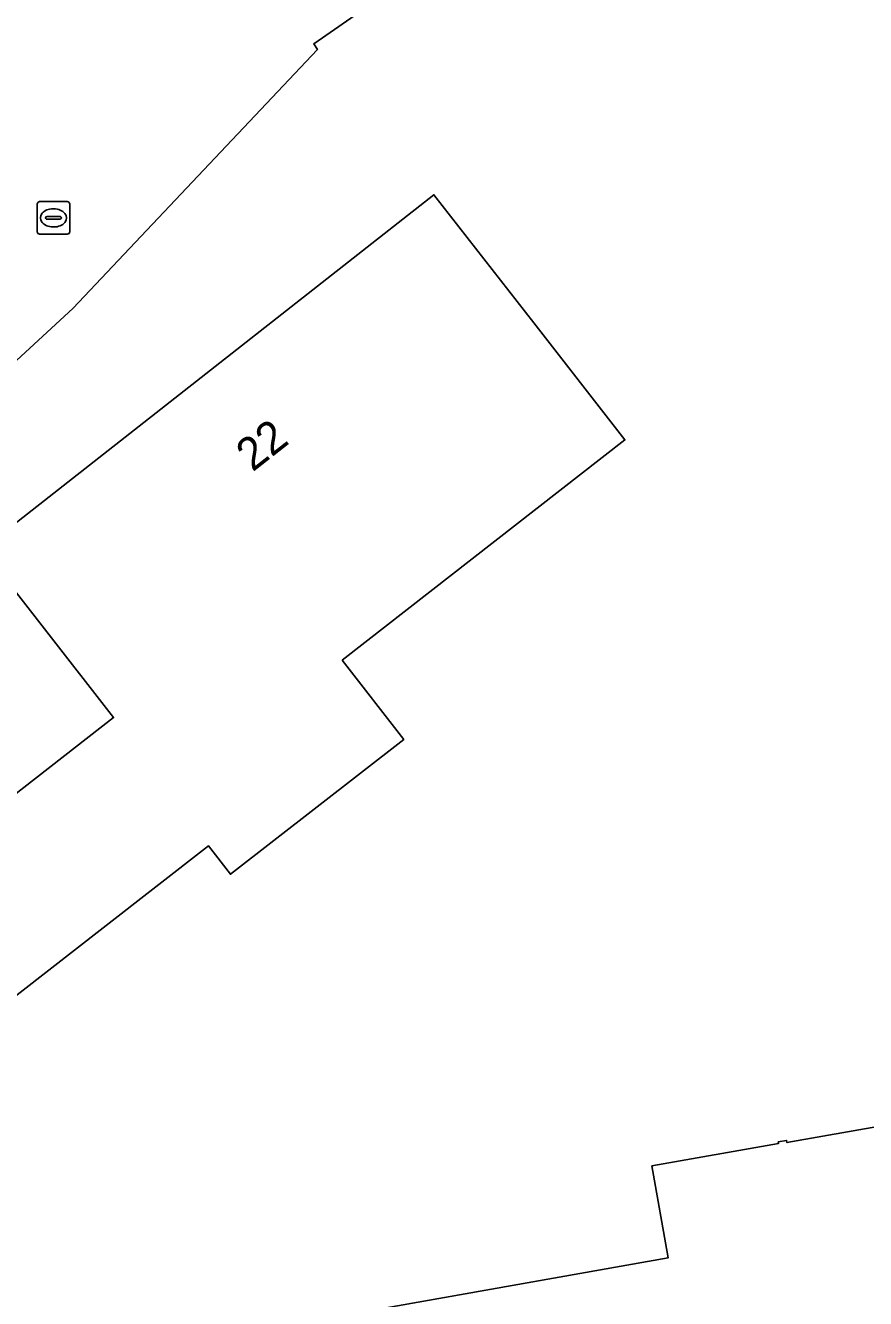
# Model space of a CAD drawing. Extents: x 162879 to 165540, y 384011 to 385181.
# Drawn here: x 164259.38 to 164285.23, y 384298.69 to 384337.86 of the extents above; entities that cross this region are included whole.
import ezdxf

# ---------------------------------------------------------------- set-up
doc = ezdxf.new("R2010")
doc.units = 0
for name, color, linetype in [('IMGEO_Brandkraan', 7, 'Continuous'), ('IMGEO_Erf', 7, 'Continuous'), ('IMGEO_Pand', 7, 'Continuous'), ('IMGEO_Pand_nummerreeks', 7, 'Continuous'), ('IMGEO_Voetpad_open', 7, 'Continuous')]:
    doc.layers.add(name, color=color, linetype=linetype)

msp = doc.modelspace()

# ---------------------------------------------------------------- linework, layer by layer
at = {"layer": 'IMGEO_Brandkraan'}
for p, q in [((164259.745, 384331.517), (164259.745, 384332.369)), ((164259.82, 384332.443), (164260.672, 384332.443)), ((164260.746, 384332.369), (164260.746, 384331.517)), ((164260.047, 384331.986), (164260.445, 384331.986)), ((164260.233, 384332.223), (164260.258, 384332.223)), ((164260.004, 384331.937), (164260.004, 384331.949)), ((164260.442, 384331.9), (164260.044, 384331.9)), ((164260.256, 384331.663), (164260.231, 384331.663)), ((164260.488, 384331.949), (164260.488, 384331.937)), ((164260.672, 384331.443), (164259.82, 384331.443))]:
    msp.add_line(p, q, dxfattribs=at)
for points in [[(164259.745, 384331.517), (164259.745, 384332.369)], [(164259.82, 384332.443), (164260.672, 384332.443)], [(164260.746, 384332.369), (164260.746, 384331.517)], [(164260.672, 384331.443), (164259.82, 384331.443)]]:
    msp.add_lwpolyline(points, dxfattribs=at)
for centre, radius, start, end in [((164259.822, 384332.367), 0.0765, 91.552, 178.448), ((164259.822, 384332.367), 0.0765, 91.552, 178.448), ((164260.67, 384332.367), 0.0765, 1.552, 88.448), ((164260.67, 384332.367), 0.0765, 1.552, 88.448), ((164260.044, 384331.946), 0.0403, 85.8775, 175.7526), ((164260.449, 384331.948), 0.0386, 1.7309, 96.639), ((164260.041, 384331.936), 0.0366, 178.938, 274.7102), ((164260.445, 384331.943), 0.043, 264.8664, 352.4533), ((164259.822, 384331.519), 0.0765, 181.552, 268.448), ((164259.822, 384331.519), 0.0765, 181.552, 268.448), ((164260.67, 384331.519), 0.0765, 271.552, 358.448), ((164260.67, 384331.519), 0.0765, 271.552, 358.448)]:
    msp.add_arc(centre, radius, start, end, dxfattribs=at)
for centre, major_axis, ratio, start_param, end_param in [((164260.232, 384331.943), (-0.387, 0.002), 0.722429, 4.712389, 7.853982), ((164260.257, 384331.943), (-0.39, 0.002), 0.717154, 1.570796, 4.712389)]:
    msp.add_ellipse(centre, major_axis=major_axis, ratio=ratio, start_param=start_param, end_param=end_param, dxfattribs=at)
at = {"layer": 'IMGEO_Erf'}
for points in [[(164295.237, 384356.554), (164274.424, 384341.583), (164268.257, 384337.301), (164268.366, 384337.124), (164260.84, 384329.156), (164251.674, 384320.699), (164245.639, 384315.799), (164245.34, 384316.175), (164244.454, 384315.55), (164241.784, 384302.243), (164241.621, 384301.03), (164245.563, 384293.433)], [(164270.198, 384298.357), (164279.159, 384299.942), (164278.658, 384302.776), (164282.557, 384303.466), (164282.548, 384303.515), (164282.804, 384303.56), (164282.817, 384303.491), (164290.458, 384304.843), (164290.597, 384304.054), (164291.704, 384304.252), (164292.271, 384301.071), (164291.159, 384300.88), (164291.589, 384298.449)]]:
    msp.add_lwpolyline(points, dxfattribs=at)
msp.add_lwpolyline([(164269.13, 384318.33), (164271.025, 384315.899), (164265.693, 384311.75), (164265.021, 384312.619), (164261.773, 384310.095), (164258.422, 384307.491), (164254.478, 384304.417), (164251.464, 384308.283), (164262.093, 384316.567), (164258.051, 384321.753), (164271.951, 384332.653), (164275.024, 384328.71), (164277.829, 384325.111)], close=True, dxfattribs=at)
at = {"layer": 'IMGEO_Pand'}
for points in [[(164269.13, 384318.33), (164277.829, 384325.111), (164275.024, 384328.71), (164271.951, 384332.653), (164258.051, 384321.753), (164262.093, 384316.567), (164251.464, 384308.283), (164254.478, 384304.417), (164258.422, 384307.491), (164261.773, 384310.095), (164265.021, 384312.619), (164265.693, 384311.75), (164271.025, 384315.899)], [(164291.704, 384304.252), (164290.597, 384304.054), (164290.458, 384304.843), (164282.817, 384303.491), (164282.804, 384303.56), (164282.548, 384303.515), (164282.557, 384303.466), (164278.658, 384302.776), (164279.159, 384299.942), (164270.198, 384298.357), (164270.831, 384294.777), (164283.929, 384297.094), (164291.589, 384298.449), (164291.159, 384300.88), (164292.271, 384301.071)]]:
    msp.add_lwpolyline(points, close=True, dxfattribs=at)
at = {"layer": 'IMGEO_Voetpad_open'}
msp.add_lwpolyline([(164239.208, 384301.296), (164239.944, 384299.935), (164241.621, 384301.03), (164241.784, 384302.243), (164244.454, 384315.55), (164245.34, 384316.175), (164245.639, 384315.799), (164251.674, 384320.699), (164260.84, 384329.156), (164268.366, 384337.124), (164268.257, 384337.301), (164274.424, 384341.583), (164272.712, 384342.789), (164281.086, 384352.605), (164286.999, 384360.158), (164288.245, 384362.997), (164290.27, 384368.322)], dxfattribs=at)

# ---------------------------------------------------------------- texts
at = {"layer": 'IMGEO_Pand_nummerreeks'}
msp.add_text('22', height=1, rotation=38.1017, dxfattribs=at).set_placement((164266.373, 384324.11))

doc.saveas('drawing.dxf')
